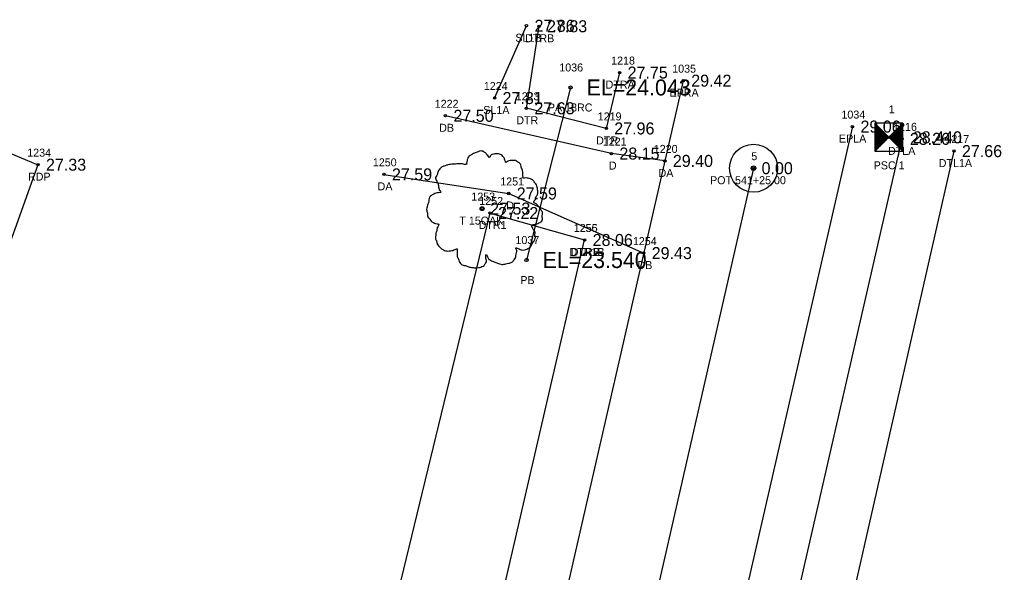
# Model space of a CAD drawing. Extents: x 2654414 to 2656963, y 761776 to 764965.
# Drawn here: x 2655958.8 to 2656081.5, y 764661.9 to 764730.9 of the extents above; entities that cross this region are included whole.
import ezdxf

# ---------------------------------------------------------------- set-up
doc = ezdxf.new("R2010")
doc.units = 0
for name, color, linetype in [('Default', 7, 'Continuous'), ('RD_EX_DR_ErosCtrl', 7, 'Continuous'), ('RD_EX_DR_ErosCtrl_txCode', 7, 'Continuous'), ('RD_EX_DR_Pipe', 7, 'Continuous'), ('RD_EX_DR_Pipe_txCode', 7, 'Continuous'), ('RD_EX_Driveway', 7, 'Continuous'), ('RD_EX_Driveway_txCode', 7, 'Continuous'), ('RD_EX_H2O', 7, 'Continuous'), ('RD_EX_H2O_txCode', 7, 'Continuous'), ('RD_EX_Road', 7, 'Continuous'), ('RD_EX_Road_txCode', 7, 'Continuous'), ('RD_EX_TX_DR_ErosCtrl_ELEV', 7, 'Continuous'), ('RD_EX_TX_Driveway_ELEV', 7, 'Continuous'), ('RD_EX_TX_H2O_ELEV', 7, 'Continuous'), ('RD_EX_TX_Road_ELEV', 7, 'Continuous'), ('RD_EX_TX_VEG_ELEV', 7, 'Continuous'), ('RD_EX_VEG', 7, 'Continuous'), ('RD_EX_VEG_txCode', 7, 'Continuous'), ('RD_HC_Cl', 7, 'Continuous'), ('RD_HC_Data', 7, 'Continuous'), ('RD_HC_Survey', 7, 'Continuous'), ('RD_HC_Survey_ELEV', 7, 'Continuous'), ('RD_HC_txCode', 7, 'Continuous'), ('RD_SMD_Locator', 7, 'Continuous'), ('RD_TX_Pipe_ElevEX', 7, 'Continuous')]:
    doc.layers.add(name, color=color, linetype=linetype)

msp = doc.modelspace()

# ---------------------------------------------------------------- linework, layer by layer
at = {"layer": 'Default'}
msp.add_line((2656050.51, 764712.37), (2655383.26, 761787.51), dxfattribs=at)
at = {"layer": 'RD_EX_DR_ErosCtrl'}
msp.add_lwpolyline([(2655930.28, 764725.72), (2655961.08, 764712.81), (2655949.1, 764679.46), (2655943.17, 764649.44), (2655951.78, 764644.09), (2655985.92, 764633.07), (2655978.62, 764588.6), (2655971.68, 764570.94), (2655934.42, 764577.78), (2655887.79, 764597.3)], dxfattribs=at)
at = {"layer": 'RD_EX_DR_Pipe'}
msp.add_line((2656027.64, 764722.46), (2656022.14, 764700.89), dxfattribs=at)
at = {"layer": 'RD_EX_Driveway'}
for points in [[(2656039.42, 764713.28), (2656032.74, 764714.2), (2656012, 764718.92)], [(2656004.32, 764711.6), (2656019.91, 764709.21), (2656036.78, 764701.76)]]:
    msp.add_lwpolyline(points, dxfattribs=at)
at = {"layer": 'RD_EX_H2O'}
for points in [[(2656033.77, 764724.32), (2656032.1, 764717.34), (2656022.12, 764719.86), (2656023.7, 764730.11)], [(2656069.04, 764716.04), (2656046.04, 764615.61), (2656043.09, 764597.03)], [(2656075.55, 764714.51), (2656052.69, 764614), (2656046.44, 764596.38), (2656043.09, 764597.03)], [(2655987.98, 764566.15), (2655998.01, 764626), (2656017.58, 764706.77), (2656029.4, 764703.4)], [(2655987.98, 764566.15), (2655988.17, 764559.49), (2655996.07, 764555.67), (2655998.72, 764566.23), (2656011.11, 764624.25), (2656029.4, 764703.4)]]:
    msp.add_lwpolyline(points, dxfattribs=at)
at = {"layer": 'RD_EX_Road'}
for points in [[(2656041.72, 764723.31), (2656018.5, 764622.03), (2656002.75, 764552.49), (2655997.43, 764530.02), (2655974.74, 764429.64), (2655952.97, 764333.57), (2655930.52, 764235.7), (2655909.18, 764142.93), (2655887.93, 764050.57), (2655866.91, 763957.26), (2655846.82, 763869.53), (2655845.21, 763862.22), (2655839.99, 763839.71), (2655823.38, 763766.66), (2655801.33, 763669.93), (2655780.03, 763576.53), (2655774.26, 763551.85), (2655771.37, 763539.86), (2655759.09, 763486.9), (2655736.94, 763391.72), (2655715.19, 763296.77), (2655711.35, 763278.45)], [(2656062.87, 764717.57), (2656039.84, 764617.04), (2656035.41, 764597.94), (2656033.38, 764589.18), (2656018.27, 764522.6), (2656017.22, 764517.64), (2656011.07, 764490.22), (2655996.52, 764425.63), (2655974.03, 764327.02), (2655960.71, 764269.34), (2655951.96, 764231.59), (2655930.84, 764138.62), (2655926.81, 764121.01), (2655909.26, 764045.26), (2655908.15, 764039.87), (2655902.08, 764013.51), (2655888.19, 763952.26), (2655880.73, 763919.6), (2655875, 763893.73), (2655866.73, 763857), (2655852.89, 763796.34), (2655850.73, 763786.52)]]:
    msp.add_lwpolyline(points, dxfattribs=at)
at = {"layer": 'RD_EX_VEG'}
msp.add_line((2656018.14, 764721.14), (2656022.13, 764730.17), dxfattribs=at)
for centre, radius in [((2656016.59, 764707.32), 0.25), ((2656016.57, 764707.31), 0.0001)]:
    msp.add_circle(centre, radius, dxfattribs=at)
for points in [[(2656016.72, 764714.49), (2656016.42, 764714.52), (2656016.09, 764714.42), (2656015.84, 764714.32), (2656015.62, 764714.24), (2656015.39, 764714.14), (2656015.09, 764713.97), (2656014.87, 764713.77), (2656014.75, 764713.52), (2656014.7, 764713.29), (2656014.65, 764713.02), (2656014.65, 764712.84), (2656014.52, 764712.82), (2656014.37, 764712.84), (2656014.12, 764712.92), (2656013.87, 764712.92), (2656013.62, 764712.92), (2656013.27, 764712.89), (2656012.92, 764712.89), (2656012.65, 764712.84), (2656012.32, 764712.79), (2656011.95, 764712.67), (2656011.6, 764712.54), (2656011.3, 764712.29), (2656011.05, 764711.82), (2656010.92, 764711.47), (2656010.77, 764711.22), (2656010.92, 764710.77), (2656011.1, 764710.42), (2656011.12, 764710.22), (2656011.2, 764709.79), (2656011.3, 764709.57), (2656011.42, 764709.37), (2656011.35, 764709.34), (2656010.97, 764709.29), (2656010.67, 764709.19), (2656010.25, 764708.97), (2656010.02, 764708.74), (2656009.92, 764708.42), (2656009.9, 764708.07), (2656009.8, 764707.87), (2656009.72, 764707.6), (2656009.7, 764707.52), (2656009.65, 764707.2), (2656009.75, 764706.75), (2656009.77, 764706.4), (2656009.9, 764706.17), (2656010.05, 764706), (2656010.22, 764705.75), (2656010.62, 764705.52), (2656010.95, 764705.42), (2656011.15, 764705.4), (2656010.97, 764704.9), (2656010.92, 764704.55), (2656010.8, 764704.15), (2656010.8, 764704.07), (2656010.75, 764703.6), (2656010.9, 764703.27), (2656010.97, 764702.9), (2656011.15, 764702.67), (2656011.42, 764702.37), (2656011.75, 764702.15), (2656012.25, 764702.02), (2656012.65, 764702.05), (2656013.22, 764702.22), (2656013.47, 764702.3), (2656013.45, 764702.12), (2656013.47, 764701.75), (2656013.47, 764701.32), (2656013.62, 764701), (2656013.72, 764700.72), (2656013.87, 764700.47), (2656014.2, 764700.25), (2656014.6, 764700.17), (2656015.02, 764700.02), (2656015.47, 764699.95), (2656015.97, 764699.92), (2656016.57, 764700.07), (2656016.84, 764700.2), (2656016.94, 764700.37), (2656017.14, 764700.75), (2656017.09, 764700.97), (2656017.12, 764701.57), (2656017.22, 764701.4), (2656017.39, 764701.05), (2656017.89, 764700.75), (2656018.29, 764700.57), (2656018.77, 764700.42), (2656019.07, 764700.35), (2656019.54, 764700.42), (2656019.92, 764700.5), (2656020.29, 764700.62), (2656020.59, 764700.9), (2656020.77, 764701.17), (2656020.82, 764701.45), (2656020.89, 764701.82), (2656020.94, 764702)], [(2656020.94, 764702), (2656020.87, 764702.17), (2656020.82, 764702.42), (2656020.89, 764702.4), (2656021.07, 764702.35), (2656021.34, 764702.22), (2656021.57, 764702.15), (2656021.89, 764702.17), (2656022.17, 764702.27), (2656022.62, 764702.55), (2656022.89, 764703.02), (2656023.17, 764703.42), (2656023.24, 764703.75), (2656023.19, 764703.97), (2656023.17, 764704.47), (2656022.97, 764704.72), (2656022.92, 764704.85), (2656022.82, 764705.25), (2656022.89, 764705.3), (2656023.17, 764705.35), (2656023.54, 764705.47), (2656023.82, 764705.6), (2656024.04, 764705.77), (2656024.12, 764706), (2656024.09, 764706.4), (2656024.14, 764706.8), (2656024.07, 764706.95), (2656023.97, 764707.1), (2656023.89, 764707.3), (2656023.74, 764707.45), (2656023.64, 764707.6), (2656023.54, 764707.7), (2656023.42, 764707.85), (2656023.24, 764707.97), (2656023.09, 764708.02), (2656023.04, 764708.17), (2656023.19, 764708.37), (2656023.24, 764708.47), (2656023.27, 764708.69), (2656023.49, 764709.04), (2656023.54, 764709.44), (2656023.49, 764709.87), (2656023.44, 764710.14), (2656023.29, 764710.42), (2656023.09, 764710.67), (2656022.97, 764710.84), (2656022.79, 764710.97), (2656022.47, 764711.09), (2656022.22, 764711.14), (2656021.87, 764711.14), (2656021.67, 764711.19), (2656021.69, 764711.24), (2656021.69, 764711.39), (2656021.69, 764711.67), (2656021.62, 764712.12), (2656021.47, 764712.62), (2656021.47, 764712.64), (2656021.37, 764712.89), (2656021.14, 764713.09), (2656020.97, 764713.19), (2656020.77, 764713.32), (2656020.52, 764713.34), (2656020.22, 764713.34), (2656019.94, 764713.29), (2656019.74, 764713.19), (2656019.57, 764713.07), (2656019.49, 764713.22), (2656019.39, 764713.52), (2656019.34, 764713.67), (2656019.19, 764713.84), (2656018.97, 764714.04), (2656018.52, 764714.17), (2656017.89, 764714.09), (2656017.59, 764713.89), (2656017.44, 764713.72), (2656017.39, 764713.84), (2656017.19, 764714.04), (2656017.09, 764714.22), (2656016.92, 764714.34), (2656016.77, 764714.44), (2656016.67, 764714.49)]]:
    msp.add_spline(points, degree=3, dxfattribs=at)
at = {"layer": 'RD_HC_Cl'}
msp.add_line((2656050.51, 764712.37), (2655383.26, 761787.51), dxfattribs=at)
at = {"layer": 'RD_HC_Data'}
for radius in [3, 0.282]:
    msp.add_circle((2656050.51, 764712.37), radius, dxfattribs=at)
at = {"layer": 'RD_HC_Survey'}
for p, q in [((2656065.66, 764717.98), (2656069.16, 764714.48)), ((2656069.16, 764717.98), (2656065.66, 764714.48)), ((2656065.68, 764717.96), (2656065.68, 764714.51)), ((2656065.71, 764717.93), (2656065.71, 764714.53)), ((2656065.73, 764717.91), (2656065.73, 764714.56)), ((2656065.76, 764717.88), (2656065.76, 764714.58)), ((2656065.78, 764717.86), (2656065.78, 764714.6)), ((2656065.81, 764717.83), (2656065.81, 764714.63)), ((2656065.83, 764717.81), (2656065.83, 764714.65)), ((2656065.86, 764717.78), (2656065.86, 764714.68)), ((2656065.88, 764717.76), (2656065.88, 764714.7)), ((2656065.91, 764717.73), (2656065.91, 764714.73)), ((2656065.93, 764717.71), (2656065.93, 764714.75)), ((2656065.95, 764717.68), (2656065.95, 764714.78)), ((2656065.98, 764717.66), (2656065.98, 764714.8)), ((2656066, 764717.63), (2656066, 764714.83)), ((2656066.03, 764717.61), (2656066.03, 764714.85)), ((2656066.05, 764717.58), (2656066.05, 764714.88)), ((2656066.08, 764717.56), (2656066.08, 764714.9)), ((2656066.1, 764717.54), (2656066.1, 764714.93)), ((2656066.13, 764717.51), (2656066.13, 764714.95)), ((2656066.15, 764717.49), (2656066.15, 764714.98)), ((2656066.18, 764717.46), (2656066.18, 764715)), ((2656066.2, 764717.44), (2656066.2, 764715.03)), ((2656066.23, 764717.41), (2656066.23, 764715.05)), ((2656066.25, 764717.39), (2656066.25, 764715.07)), ((2656066.28, 764717.36), (2656066.28, 764715.1)), ((2656066.3, 764717.34), (2656066.3, 764715.12)), ((2656066.33, 764717.31), (2656066.33, 764715.15)), ((2656066.35, 764717.29), (2656066.35, 764715.17)), ((2656066.38, 764717.26), (2656066.38, 764715.2)), ((2656066.4, 764717.24), (2656066.4, 764715.22)), ((2656066.42, 764717.21), (2656066.42, 764715.25)), ((2656066.45, 764717.19), (2656066.45, 764715.27)), ((2656066.47, 764717.16), (2656066.47, 764715.3)), ((2656066.5, 764717.14), (2656066.5, 764715.32)), ((2656066.52, 764717.11), (2656066.52, 764715.35)), ((2656066.55, 764717.09), (2656066.55, 764715.37)), ((2656066.57, 764717.07), (2656066.57, 764715.4)), ((2656068.24, 764717.07), (2656068.24, 764715.4)), ((2656068.27, 764717.09), (2656068.27, 764715.37)), ((2656068.29, 764717.11), (2656068.29, 764715.35)), ((2656068.32, 764717.14), (2656068.32, 764715.32)), ((2656068.34, 764717.16), (2656068.34, 764715.3)), ((2656068.37, 764717.19), (2656068.37, 764715.27)), ((2656068.39, 764717.21), (2656068.39, 764715.25)), ((2656068.42, 764717.24), (2656068.42, 764715.22)), ((2656068.44, 764717.26), (2656068.44, 764715.2)), ((2656068.46, 764717.29), (2656068.46, 764715.17)), ((2656068.49, 764717.31), (2656068.49, 764715.15)), ((2656068.51, 764717.34), (2656068.51, 764715.12)), ((2656068.54, 764717.36), (2656068.54, 764715.1)), ((2656068.56, 764717.39), (2656068.56, 764715.07)), ((2656068.59, 764717.41), (2656068.59, 764715.05)), ((2656068.61, 764717.44), (2656068.61, 764715.03)), ((2656068.64, 764717.46), (2656068.64, 764715)), ((2656068.66, 764717.49), (2656068.66, 764714.98)), ((2656068.69, 764717.51), (2656068.69, 764714.95)), ((2656068.71, 764717.54), (2656068.71, 764714.93)), ((2656068.74, 764717.56), (2656068.74, 764714.9)), ((2656068.76, 764717.58), (2656068.76, 764714.88)), ((2656068.79, 764717.61), (2656068.79, 764714.85)), ((2656068.81, 764717.63), (2656068.81, 764714.83)), ((2656068.84, 764717.66), (2656068.84, 764714.8)), ((2656068.86, 764717.68), (2656068.86, 764714.78)), ((2656068.89, 764717.71), (2656068.89, 764714.75)), ((2656068.91, 764717.73), (2656068.91, 764714.73)), ((2656068.93, 764717.76), (2656068.93, 764714.7)), ((2656068.96, 764717.78), (2656068.96, 764714.68)), ((2656068.98, 764717.81), (2656068.98, 764714.65)), ((2656069.01, 764717.83), (2656069.01, 764714.63)), ((2656069.03, 764717.86), (2656069.03, 764714.6)), ((2656069.06, 764717.88), (2656069.06, 764714.58)), ((2656069.08, 764717.91), (2656069.08, 764714.56)), ((2656069.11, 764717.93), (2656069.11, 764714.53)), ((2656069.13, 764717.96), (2656069.13, 764714.51)), ((2656066.6, 764717.04), (2656066.6, 764715.42)), ((2656066.62, 764717.02), (2656066.62, 764715.45)), ((2656066.65, 764716.99), (2656066.65, 764715.47)), ((2656066.67, 764716.97), (2656066.67, 764715.5)), ((2656066.7, 764716.94), (2656066.7, 764715.52)), ((2656066.72, 764716.92), (2656066.72, 764715.54)), ((2656066.75, 764716.89), (2656066.75, 764715.57)), ((2656066.77, 764716.87), (2656066.77, 764715.59)), ((2656066.8, 764716.84), (2656066.8, 764715.62)), ((2656066.82, 764716.82), (2656066.82, 764715.64)), ((2656066.85, 764716.79), (2656066.85, 764715.67)), ((2656066.87, 764716.77), (2656066.87, 764715.69)), ((2656066.9, 764716.74), (2656066.9, 764715.72)), ((2656066.92, 764716.72), (2656066.92, 764715.74)), ((2656066.94, 764716.69), (2656066.94, 764715.77)), ((2656066.97, 764716.67), (2656066.97, 764715.79)), ((2656066.99, 764716.64), (2656066.99, 764715.82)), ((2656067.02, 764716.62), (2656067.02, 764715.84)), ((2656067.04, 764716.59), (2656067.04, 764715.87)), ((2656067.07, 764716.57), (2656067.07, 764715.89)), ((2656067.09, 764716.55), (2656067.09, 764715.92)), ((2656067.12, 764716.52), (2656067.12, 764715.94)), ((2656067.14, 764716.5), (2656067.14, 764715.97)), ((2656067.17, 764716.47), (2656067.17, 764715.99)), ((2656067.19, 764716.45), (2656067.19, 764716.02)), ((2656067.22, 764716.42), (2656067.22, 764716.04)), ((2656067.24, 764716.4), (2656067.24, 764716.06)), ((2656067.27, 764716.37), (2656067.27, 764716.09)), ((2656067.29, 764716.35), (2656067.29, 764716.11)), ((2656067.32, 764716.32), (2656067.32, 764716.14)), ((2656067.34, 764716.3), (2656067.34, 764716.16)), ((2656067.37, 764716.27), (2656067.37, 764716.19)), ((2656067.39, 764716.25), (2656067.39, 764716.21)), ((2656067.43, 764716.25), (2656067.43, 764716.21)), ((2656067.45, 764716.27), (2656067.45, 764716.19)), ((2656067.47, 764716.3), (2656067.47, 764716.16)), ((2656067.5, 764716.32), (2656067.5, 764716.14)), ((2656067.52, 764716.35), (2656067.52, 764716.11)), ((2656067.55, 764716.37), (2656067.55, 764716.09)), ((2656067.57, 764716.4), (2656067.57, 764716.06)), ((2656067.6, 764716.42), (2656067.6, 764716.04)), ((2656067.62, 764716.45), (2656067.62, 764716.02)), ((2656067.65, 764716.47), (2656067.65, 764715.99)), ((2656067.67, 764716.5), (2656067.67, 764715.97)), ((2656067.7, 764716.52), (2656067.7, 764715.94)), ((2656067.72, 764716.55), (2656067.72, 764715.92)), ((2656067.75, 764716.57), (2656067.75, 764715.89)), ((2656067.77, 764716.59), (2656067.77, 764715.87)), ((2656067.8, 764716.62), (2656067.8, 764715.84)), ((2656067.82, 764716.64), (2656067.82, 764715.82)), ((2656067.85, 764716.67), (2656067.85, 764715.79)), ((2656067.87, 764716.69), (2656067.87, 764715.77)), ((2656067.9, 764716.72), (2656067.9, 764715.74)), ((2656067.92, 764716.74), (2656067.92, 764715.72)), ((2656067.94, 764716.77), (2656067.94, 764715.69)), ((2656067.97, 764716.79), (2656067.97, 764715.67)), ((2656067.99, 764716.82), (2656067.99, 764715.64)), ((2656068.02, 764716.84), (2656068.02, 764715.62)), ((2656068.04, 764716.87), (2656068.04, 764715.59)), ((2656068.07, 764716.89), (2656068.07, 764715.57)), ((2656068.09, 764716.92), (2656068.09, 764715.54)), ((2656068.12, 764716.94), (2656068.12, 764715.52)), ((2656068.14, 764716.97), (2656068.14, 764715.5)), ((2656068.17, 764716.99), (2656068.17, 764715.47)), ((2656068.19, 764717.02), (2656068.19, 764715.45)), ((2656068.22, 764717.04), (2656068.22, 764715.42))]:
    msp.add_line(p, q, dxfattribs=at)
msp.add_lwpolyline([(2656069.16, 764717.98), (2656065.66, 764717.98), (2656065.66, 764714.48), (2656069.16, 764714.48)], close=True, dxfattribs=at)
at = {"layer": 'RD_SMD_Locator'}
for centre, radius in [((2656022.13, 764730.17), 0.15), ((2656023.7, 764730.11), 0.15), ((2656033.77, 764724.32), 0.15), ((2656041.72, 764723.31), 0.15), ((2656027.64, 764722.46), 0.2), ((2656018.14, 764721.14), 0.15), ((2656022.12, 764719.86), 0.15), ((2656012, 764718.92), 0.15), ((2656032.1, 764717.34), 0.15), ((2656062.87, 764717.57), 0.15), ((2656067.41, 764716.23), 0.15), ((2656069.04, 764716.04), 0.15), ((2656075.55, 764714.51), 0.15), ((2656032.74, 764714.2), 0.15), ((2656039.42, 764713.28), 0.15), ((2655961.08, 764712.81), 0.15), ((2656050.51, 764712.37), 0.15), ((2656004.32, 764711.6), 0.15), ((2656019.91, 764709.21), 0.15), ((2656016.59, 764707.32), 0.15), ((2656017.58, 764706.77), 0.15), ((2656029.4, 764703.4), 0.15), ((2656029.4, 764703.4), 0.15), ((2656036.78, 764701.76), 0.15), ((2656022.14, 764700.89), 0.2)]:
    msp.add_circle(centre, radius, dxfattribs=at)

# ---------------------------------------------------------------- texts
at = {"layer": 'RD_EX_DR_ErosCtrl_txCode'}
for s, p in [('1234', (2655959.74, 764713.81)), ('RDP', (2655959.83, 764710.81))]:
    msp.add_text(s, height=1, dxfattribs=at).set_placement(p)
at = {"layer": 'RD_EX_DR_Pipe_txCode'}
for s, p in [('1036', (2656026.23, 764724.46)), ('PA 18RC', (2656024.8, 764719.46)), ('1037', (2656020.75, 764702.89)), ('PB', (2656021.36, 764697.89))]:
    msp.add_text(s, height=1, dxfattribs=at).set_placement(p)
at = {"layer": 'RD_EX_Driveway_txCode'}
for s, p in [('1222', (2656010.66, 764719.92)), ('DB', (2656011.22, 764716.92)), ('1221', (2656031.67, 764715.2)), ('1220', (2656038.04, 764714.28)), ('1250', (2656002.93, 764712.6)), ('D', (2656032.43, 764712.2)), ('DA', (2656038.63, 764711.28)), ('1251', (2656018.85, 764710.21)), ('DA', (2656003.52, 764709.6)), ('D', (2656019.6, 764707.21)), ('1254', (2656035.43, 764702.76)), ('DB', (2656036, 764699.76))]:
    msp.add_text(s, height=1, dxfattribs=at).set_placement(p)
at = {"layer": 'RD_EX_H2O_txCode'}
for s, p in [('DTRB', (2656021.96, 764728.11)), ('1218', (2656032.71, 764725.32)), ('DTRA', (2656032.02, 764722.32)), ('1223', (2656020.78, 764720.86)), ('DTR', (2656020.86, 764717.86)), ('1219', (2656031.03, 764718.34)), ('1216', (2656067.95, 764717.04)), ('DTR', (2656030.83, 764715.34)), ('1217', (2656074.48, 764715.51)), ('DTLA', (2656067.31, 764714.04)), ('DTL1A', (2656073.65, 764712.51)), ('1252', (2656016.23, 764707.77)), ('DTR1', (2656016.15, 764704.77)), ('1256', (2656028.03, 764704.4)), ('1255', (2656028.05, 764704.4)), ('DTR1B', (2656027.5, 764701.4)), ('DTRB', (2656027.66, 764701.4))]:
    msp.add_text(s, height=1, dxfattribs=at).set_placement(p)
at = {"layer": 'RD_EX_Road_txCode'}
for s, p in [('1035', (2656040.34, 764724.31)), ('EPRA', (2656040.01, 764721.31)), ('1034', (2656061.49, 764718.57)), ('EPLA', (2656061.18, 764715.57))]:
    msp.add_text(s, height=1, dxfattribs=at).set_placement(p)
at = {"layer": 'RD_EX_TX_DR_ErosCtrl_ELEV'}
msp.add_text('27.33', height=1.5, dxfattribs=at).set_placement((2655962.08, 764712.06))
at = {"layer": 'RD_EX_TX_Driveway_ELEV'}
for s, p in [('27.50', (2656013, 764718.17)), ('28.15', (2656033.74, 764713.45)), ('29.40', (2656040.42, 764712.53)), ('27.59', (2656005.32, 764710.85)), ('27.59', (2656020.91, 764708.46)), ('29.43', (2656037.78, 764701.01))]:
    msp.add_text(s, height=1.5, dxfattribs=at).set_placement(p)
at = {"layer": 'RD_EX_TX_H2O_ELEV'}
for s, p in [('27.83', (2656024.7, 764729.36)), ('27.75', (2656034.77, 764723.57)), ('27.63', (2656023.12, 764719.11)), ('27.96', (2656033.1, 764716.59)), ('28.26', (2656070.04, 764715.29)), ('27.66', (2656076.55, 764713.76)), ('27.22', (2656018.58, 764706.02)), ('28.06', (2656030.4, 764702.65)), ('28.06', (2656030.4, 764702.65))]:
    msp.add_text(s, height=1.5, dxfattribs=at).set_placement(p)
at = {"layer": 'RD_EX_TX_Road_ELEV'}
for s, p in [('29.42', (2656042.72, 764722.56)), ('29.06', (2656063.87, 764716.82))]:
    msp.add_text(s, height=1.5, dxfattribs=at).set_placement(p)
at = {"layer": 'RD_EX_TX_VEG_ELEV'}
for s, p in [('27.86', (2656023.13, 764729.42)), ('27.81', (2656019.14, 764720.39)), ('27.53', (2656017.59, 764706.57))]:
    msp.add_text(s, height=1.5, dxfattribs=at).set_placement(p)
at = {"layer": 'RD_EX_VEG_txCode'}
for s, p in [('SL1B', (2656020.74, 764728.17)), ('1224', (2656016.8, 764722.14)), ('SL1A', (2656016.73, 764719.14)), ('1253', (2656015.24, 764708.32)), ('T 15OAK', (2656013.74, 764705.32))]:
    msp.add_text(s, height=1, dxfattribs=at).set_placement(p)
at = {"layer": 'RD_HC_Survey_ELEV'}
for s, p in [('28.440', (2656070.41, 764715.48)), ('0.00', (2656051.51, 764711.62))]:
    msp.add_text(s, height=1.5, dxfattribs=at).set_placement(p)
at = {"layer": 'RD_HC_txCode'}
for s, p in [('1', (2656067.41, 764719.23)), ('5', (2656050.23, 764713.37)), ('PSC 1', (2656065.52, 764712.23)), ('POT 541+25.00', (2656045.07, 764710.37))]:
    msp.add_text(s, height=1, dxfattribs=at).set_placement(p)
at = {"layer": 'RD_TX_Pipe_ElevEX'}
for s, p in [('EL=24.043', (2656029.64, 764721.46)), ('EL=23.540', (2656024.14, 764699.89))]:
    msp.add_text(s, height=2, dxfattribs=at).set_placement(p)

doc.saveas('drawing.dxf')
